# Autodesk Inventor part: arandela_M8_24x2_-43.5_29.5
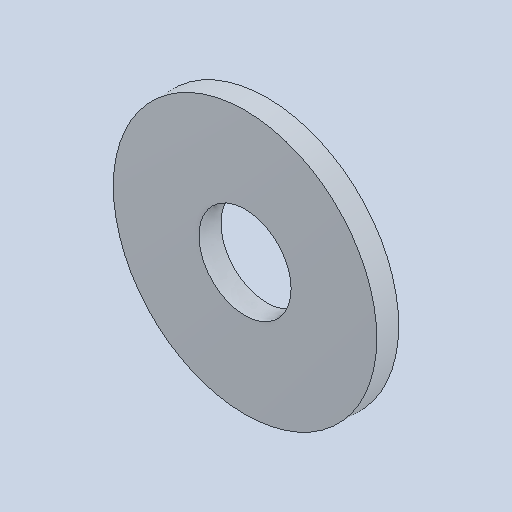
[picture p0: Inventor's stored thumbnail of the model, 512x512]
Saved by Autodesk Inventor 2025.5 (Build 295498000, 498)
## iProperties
Created: 2026-10
Part Number: arandela_M8_24x2_-43.5_29.5
Material: Genérico
Document SubType Name: Modeling
Designer: Luis M
Density: 1 g/cm^3
Appearance: Valor por defecto
Author: Luis M
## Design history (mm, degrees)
feature "Base1"
node "Sólido1"
